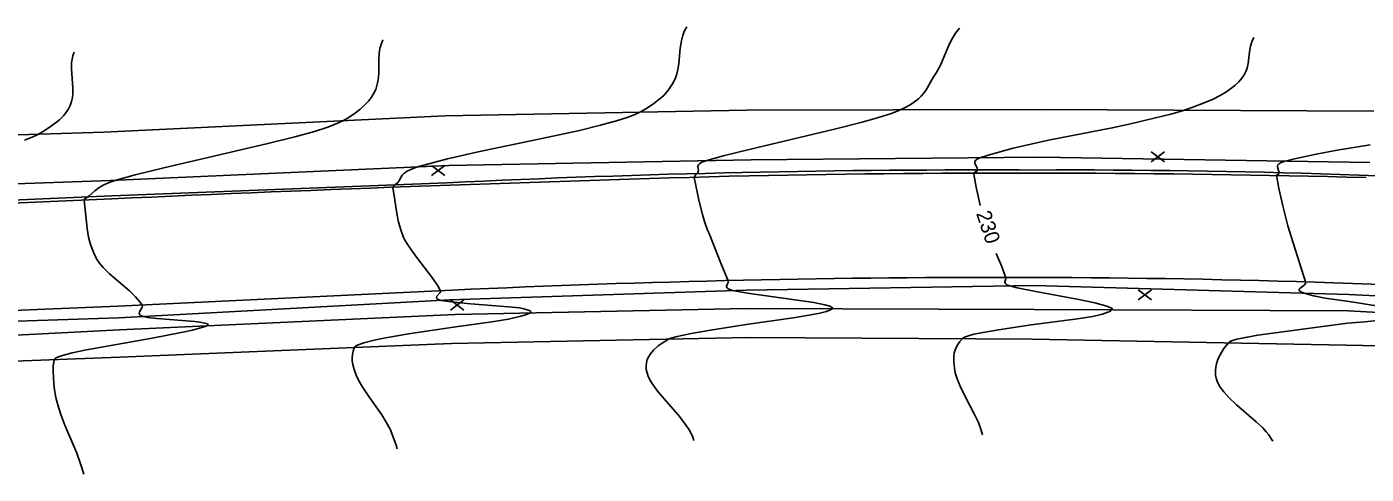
# Model space of a CAD drawing. Extents: x -593772 to -592667, y -1183541 to -1183371.
# Drawn here: x -593539.2 to -593464.5, y -1183400.6 to -1183375.6 of the extents above; entities that cross this region are included whole.
import ezdxf

# ---------------------------------------------------------------- set-up
doc = ezdxf.new("R2010")
doc.units = 0
for name, color, linetype in [('bez obruby', 7, 'Continuous'), ('hlavni vrstevnice', 7, 'Continuous'), ('svisle dopravni znaceni', 7, 'Continuous'), ('terenni hrany', 7, 'Continuous'), ('vodorovne dopravni znaceni', 7, 'Continuous'), ('vrstevnice', 7, 'Continuous')]:
    doc.layers.add(name, color=color, linetype=linetype)

msp = doc.modelspace()

# ---------------------------------------------------------------- linework, layer by layer
at = {"layer": 'bez obruby'}
for p, q in [((-593515.74, -1183384.35), (-593534.44, -1183385.09)), ((-593534.44, -1183385.09), (-593551.89, -1183385.85)), ((-593515.44, -1183390.35), (-593534.11, -1183391.25)), ((-593534.11, -1183391.25), (-593551.68, -1183391.97))]:
    msp.add_line(p, q, dxfattribs=at)
for centre, radius, start, end in [((-593485.761, -1184010.691), 627.058, 89.728524, 92.74029), ((-593480.94, -1183831.828), 448.192, 85.92367, 90.23652), ((-593484.766, -1184050.264), 660.627, 89.84248, 92.661277), ((-593484.14, -1183918.086), 528.447, 86.25017, 89.87092)]:
    msp.add_arc(centre, radius, start, end, dxfattribs=at)
at = {"layer": 'hlavni vrstevnice'}
for points in [[(-593470.724, -1183376.237), (-593470.837, -1183376.474), (-593470.915, -1183376.726), (-593470.97, -1183377.046), (-593471.042, -1183377.693), (-593471.096, -1183377.947), (-593471.16, -1183378.136), (-593471.251, -1183378.318), (-593471.384, -1183378.507), (-593471.56, -1183378.708), (-593471.78, -1183378.916), (-593472.018, -1183379.109), (-593472.29, -1183379.296), (-593472.598, -1183379.477), (-593472.984, -1183379.675), (-593473.486, -1183379.896), (-593474.116, -1183380.134), (-593474.703, -1183380.328), (-593475.359, -1183380.514), (-593477.674, -1183381.076), (-593478.623, -1183381.285), (-593482.177, -1183381.978), (-593482.752, -1183382.1), (-593484.149, -1183382.429), (-593484.946, -1183382.637), (-593485.599, -1183382.827), (-593486.005, -1183382.96), (-593486.162, -1183383.03), (-593486.254, -1183383.101), (-593486.294, -1183383.173), (-593486.295, -1183383.233), (-593486.251, -1183383.342), (-593486.158, -1183383.524), (-593486.136, -1183383.629), (-593486.146, -1183383.669), (-593486.328, -1183383.803), (-593486.333, -1183383.863), (-593486.21, -1183384.601), (-593486.028, -1183385.441), (-593485.983, -1183385.619)], [(-593485.088, -1183388.297), (-593484.791, -1183388.994), (-593484.552, -1183389.657), (-593484.554, -1183389.724), (-593484.613, -1183389.885), (-593484.613, -1183389.923), (-593484.584, -1183389.985), (-593484.504, -1183390.046), (-593484.342, -1183390.116), (-593483.924, -1183390.227), (-593482.888, -1183390.429), (-593480.485, -1183390.874), (-593479.594, -1183391.066), (-593478.92, -1183391.251), (-593478.697, -1183391.336), (-593478.627, -1183391.38), (-593478.608, -1183391.41), (-593478.615, -1183391.44), (-593478.715, -1183391.519), (-593478.864, -1183391.59), (-593479.166, -1183391.689), (-593479.718, -1183391.815), (-593480.565, -1183391.954), (-593483.142, -1183392.293), (-593484.967, -1183392.561), (-593485.828, -1183392.71), (-593486.336, -1183392.818), (-593486.702, -1183392.92), (-593486.856, -1183392.98), (-593486.961, -1183393.041), (-593487.116, -1183393.211), (-593487.279, -1183393.452), (-593487.37, -1183393.646), (-593487.43, -1183393.848), (-593487.461, -1183394.045), (-593487.466, -1183394.332), (-593487.427, -1183394.705), (-593487.375, -1183394.961), (-593487.27, -1183395.298), (-593487.102, -1183395.707), (-593486.817, -1183396.285), (-593486.315, -1183397.253), (-593486.088, -1183397.747), (-593485.946, -1183398.122), (-593485.857, -1183398.427)]]:
    msp.add_lwpolyline(points, dxfattribs=at)
at = {"layer": 'svisle dopravni znaceni'}
for p, q in [((-593476.455, -1183383.181), (-593475.705, -1183382.619)), ((-593476.455, -1183382.619), (-593475.705, -1183383.181)), ((-593516.605, -1183383.951), (-593515.855, -1183383.389)), ((-593516.605, -1183383.389), (-593515.855, -1183383.951)), ((-593515.545, -1183391.461), (-593514.795, -1183390.899)), ((-593515.545, -1183390.899), (-593514.795, -1183391.461)), ((-593477.175, -1183390.891), (-593476.425, -1183390.329)), ((-593477.175, -1183390.329), (-593476.425, -1183390.891))]:
    msp.add_line(p, q, dxfattribs=at)
at = {"layer": 'terenni hrany'}
for p, q in [((-593499.03, -1183380.29), (-593515.83, -1183380.62)), ((-593482.62, -1183380.26), (-593499.03, -1183380.29)), ((-593464.02, -1183380.35), (-593482.62, -1183380.26)), ((-593515.83, -1183380.62), (-593534.88, -1183381.52)), ((-593534.88, -1183381.52), (-593551.71, -1183382.08)), ((-593515.64, -1183383.39), (-593534.51, -1183384.22)), ((-593498.76, -1183383.07), (-593515.64, -1183383.39)), ((-593482.66, -1183382.92), (-593498.76, -1183383.07)), ((-593464.25, -1183383.22), (-593482.66, -1183382.92)), ((-593534.51, -1183384.22), (-593551.8, -1183384.86)), ((-593482.98, -1183390.1), (-593499.02, -1183390.35)), ((-593465.42, -1183390.59), (-593482.98, -1183390.1)), ((-593515.6, -1183390.89), (-593534.05, -1183391.89)), ((-593499.02, -1183390.35), (-593515.6, -1183390.89)), ((-593449.51, -1183391.42), (-593465.42, -1183390.59)), ((-593499.03, -1183391.37), (-593515.28, -1183391.71)), ((-593482.97, -1183391.43), (-593499.03, -1183391.37)), ((-593465.44, -1183391.5), (-593482.97, -1183391.43)), ((-593449.59, -1183392.38), (-593465.44, -1183391.5)), ((-593534.05, -1183391.89), (-593551.71, -1183392.47)), ((-593515.28, -1183391.71), (-593534.01, -1183392.56)), ((-593534.01, -1183392.56), (-593551.8, -1183393.5)), ((-593498.92, -1183393), (-593515.48, -1183393.33)), ((-593483.08, -1183393.08), (-593498.92, -1183393)), ((-593465.57, -1183393.42), (-593483.08, -1183393.08)), ((-593515.48, -1183393.33), (-593533.98, -1183394.1)), ((-593449.56, -1183393.79), (-593465.57, -1183393.42)), ((-593533.98, -1183394.1), (-593551.65, -1183394.76))]:
    msp.add_line(p, q, dxfattribs=at)
at = {"layer": 'vodorovne dopravni znaceni'}
msp.add_line((-593534.44, -1183385.25), (-593551.87, -1183386.03), dxfattribs=at)
for centre, radius, start, end in [((-593445.258, -1185352.875), 1969.645, 91.560035, 92.595148), ((-593483.843, -1184133.894), 750.085, 88.518486, 91.14869)]:
    msp.add_arc(centre, radius, start, end, dxfattribs=at)
at = {"layer": 'vrstevnice'}
for points in [[(-593502.354, -1183375.638), (-593502.478, -1183375.873), (-593502.574, -1183376.111), (-593502.66, -1183376.427), (-593502.722, -1183376.827), (-593502.802, -1183377.712), (-593502.854, -1183378.032), (-593502.938, -1183378.349), (-593503.026, -1183378.581), (-593503.146, -1183378.818), (-593503.373, -1183379.158), (-593503.647, -1183379.469), (-593503.932, -1183379.728), (-593504.193, -1183379.93), (-593504.548, -1183380.165), (-593504.91, -1183380.375), (-593505.059, -1183380.452), (-593505.288, -1183380.556), (-593505.692, -1183380.71), (-593506.273, -1183380.896), (-593507.173, -1183381.142), (-593508.349, -1183381.425), (-593510.349, -1183381.86), (-593513.994, -1183382.621), (-593515.711, -1183383.014), (-593516.756, -1183383.289), (-593517.38, -1183383.47), (-593517.716, -1183383.588), (-593517.962, -1183383.705), (-593518.127, -1183383.819), (-593518.233, -1183383.933), (-593518.423, -1183384.272), (-593518.475, -1183384.337), (-593518.633, -1183384.466), (-593518.745, -1183384.571), (-593518.754, -1183384.619), (-593518.663, -1183385.199), (-593518.543, -1183386.069), (-593518.445, -1183386.554), (-593518.301, -1183387.04), (-593518.154, -1183387.407), (-593518.099, -1183387.52), (-593517.875, -1183387.877), (-593517.493, -1183388.427), (-593516.531, -1183389.695), (-593516.255, -1183390.106), (-593516.092, -1183390.39), (-593516.088, -1183390.434), (-593516.128, -1183390.507), (-593516.3, -1183390.691), (-593516.326, -1183390.763), (-593516.304, -1183390.816), (-593516.23, -1183390.867), (-593516.061, -1183390.923), (-593515.494, -1183391.01), (-593514.426, -1183391.107), (-593512.305, -1183391.274), (-593511.683, -1183391.348), (-593511.454, -1183391.391), (-593511.204, -1183391.462), (-593511.099, -1183391.509), (-593511.047, -1183391.557), (-593511.051, -1183391.591), (-593511.116, -1183391.64), (-593511.302, -1183391.72), (-593511.618, -1183391.813), (-593512.303, -1183391.963), (-593513.24, -1183392.117), (-593515.372, -1183392.411), (-593517.883, -1183392.799), (-593519.264, -1183393.041), (-593519.802, -1183393.151), (-593520.375, -1183393.295), (-593520.695, -1183393.406), (-593520.844, -1183393.485), (-593520.897, -1183393.536), (-593520.919, -1183393.573), (-593520.977, -1183393.755), (-593521.014, -1183393.939), (-593521.028, -1183394.126), (-593521.022, -1183394.314), (-593520.996, -1183394.506), (-593520.923, -1183394.792), (-593520.811, -1183395.093), (-593520.671, -1183395.385), (-593520.435, -1183395.791), (-593520.099, -1183396.294), (-593519.378, -1183397.312), (-593519.122, -1183397.717), (-593518.913, -1183398.124), (-593518.703, -1183398.647), (-593518.58, -1183399.016), (-593518.525, -1183399.217)], [(-593487.14, -1183375.724), (-593487.356, -1183376.002), (-593487.533, -1183376.28), (-593487.718, -1183376.631), (-593488.211, -1183377.776), (-593488.429, -1183378.2), (-593488.603, -1183378.481), (-593488.996, -1183379.156), (-593489.155, -1183379.371), (-593489.283, -1183379.516), (-593489.432, -1183379.659), (-593489.651, -1183379.832), (-593489.896, -1183379.994), (-593490.216, -1183380.169), (-593490.48, -1183380.296), (-593490.933, -1183380.475), (-593491.669, -1183380.715), (-593492.58, -1183380.974), (-593494.116, -1183381.366), (-593498.882, -1183382.501), (-593500.33, -1183382.855), (-593501.293, -1183383.123), (-593501.51, -1183383.206), (-593501.646, -1183383.287), (-593501.709, -1183383.357), (-593501.735, -1183383.438), (-593501.707, -1183383.695), (-593501.744, -1183383.787), (-593501.849, -1183383.9), (-593501.934, -1183384.017), (-593501.939, -1183384.055), (-593501.667, -1183385.4), (-593501.484, -1183386.132), (-593501.365, -1183386.525), (-593501.217, -1183386.949), (-593501.076, -1183387.281), (-593500.461, -1183388.838), (-593500.053, -1183389.827), (-593500.043, -1183389.883), (-593500.075, -1183389.974), (-593500.142, -1183390.108), (-593500.145, -1183390.174), (-593500.113, -1183390.229), (-593500.04, -1183390.283), (-593499.853, -1183390.354), (-593499.605, -1183390.411), (-593498.974, -1183390.513), (-593496.58, -1183390.848), (-593495.266, -1183391.045), (-593494.651, -1183391.166), (-593494.375, -1183391.246), (-593494.24, -1183391.319), (-593494.224, -1183391.354), (-593494.244, -1183391.39), (-593494.336, -1183391.449), (-593494.569, -1183391.54), (-593494.929, -1183391.635), (-593495.428, -1183391.738), (-593496.43, -1183391.905), (-593499.047, -1183392.27), (-593501.042, -1183392.581), (-593502.109, -1183392.772), (-593502.893, -1183392.935), (-593503.25, -1183393.036), (-593503.37, -1183393.087), (-593503.731, -1183393.306), (-593503.957, -1183393.469), (-593504.219, -1183393.705), (-593504.387, -1183393.905), (-593504.481, -1183394.049), (-593504.561, -1183394.226), (-593504.61, -1183394.407), (-593504.628, -1183394.592), (-593504.616, -1183394.781), (-593504.574, -1183394.975), (-593504.504, -1183395.174), (-593504.365, -1183395.45), (-593504.22, -1183395.681), (-593503.969, -1183396.02), (-593503.509, -1183396.559), (-593502.842, -1183397.321), (-593502.434, -1183397.85), (-593502.23, -1183398.156), (-593502.081, -1183398.43), (-593502.018, -1183398.569), (-593501.957, -1183398.748)], [(-593519.31, -1183376.368), (-593519.415, -1183376.63), (-593519.475, -1183376.847), (-593519.522, -1183377.141), (-593519.543, -1183377.511), (-593519.547, -1183378.255), (-593519.58, -1183378.624), (-593519.642, -1183378.917), (-593519.715, -1183379.136), (-593519.813, -1183379.349), (-593519.946, -1183379.567), (-593520.12, -1183379.795), (-593520.372, -1183380.063), (-593520.603, -1183380.269), (-593520.909, -1183380.501), (-593521.296, -1183380.751), (-593521.542, -1183380.891), (-593521.924, -1183381.068), (-593522.447, -1183381.264), (-593523.133, -1183381.484), (-593524.228, -1183381.79), (-593525.802, -1183382.185), (-593531.531, -1183383.514), (-593533.127, -1183383.914), (-593534.197, -1183384.214), (-593534.531, -1183384.325), (-593534.878, -1183384.471), (-593535.142, -1183384.619), (-593535.376, -1183384.797), (-593535.708, -1183385.076), (-593535.834, -1183385.167), (-593535.959, -1183385.269), (-593535.978, -1183385.318), (-593535.808, -1183386.913), (-593535.729, -1183387.386), (-593535.621, -1183387.809), (-593535.465, -1183388.235), (-593535.284, -1183388.603), (-593535.139, -1183388.824), (-593534.918, -1183389.087), (-593534.567, -1183389.431), (-593533.459, -1183390.392), (-593533.107, -1183390.733), (-593532.876, -1183390.998), (-593532.737, -1183391.186), (-593532.724, -1183391.231), (-593532.741, -1183391.307), (-593532.895, -1183391.558), (-593532.912, -1183391.634), (-593532.893, -1183391.698), (-593532.827, -1183391.76), (-593532.686, -1183391.824), (-593532.453, -1183391.875), (-593531.922, -1183391.937), (-593529.804, -1183392.099), (-593529.418, -1183392.151), (-593529.186, -1183392.205), (-593529.102, -1183392.241), (-593529.07, -1183392.281), (-593529.087, -1183392.31), (-593529.181, -1183392.359), (-593529.423, -1183392.444), (-593529.942, -1183392.58), (-593530.558, -1183392.716), (-593532.194, -1183393.036), (-593535.858, -1183393.692), (-593536.653, -1183393.858), (-593537.191, -1183393.997), (-593537.468, -1183394.097), (-593537.583, -1183394.159), (-593537.624, -1183394.19), (-593537.66, -1183394.264), (-593537.702, -1183394.574), (-593537.71, -1183394.882), (-593537.671, -1183395.59), (-593537.639, -1183395.916), (-593537.564, -1183396.343), (-593537.457, -1183396.765), (-593537.287, -1183397.291), (-593537.052, -1183397.901), (-593536.394, -1183399.463), (-593536.175, -1183400.057), (-593536.007, -1183400.634)], [(-593536.545, -1183377.065), (-593536.609, -1183377.263), (-593536.653, -1183377.454), (-593536.682, -1183377.681), (-593536.687, -1183377.986), (-593536.604, -1183379.065), (-593536.609, -1183379.37), (-593536.636, -1183379.597), (-593536.687, -1183379.821), (-593536.767, -1183380.045), (-593536.875, -1183380.262), (-593537.018, -1183380.472), (-593537.135, -1183380.614), (-593537.354, -1183380.833), (-593537.52, -1183380.973), (-593537.854, -1183381.219), (-593538.26, -1183381.483), (-593538.599, -1183381.679), (-593538.881, -1183381.81), (-593539.299, -1183381.969)], [(-593464.222, -1183382.24), (-593466.072, -1183382.54), (-593467.241, -1183382.764), (-593468.46, -1183383.019), (-593468.978, -1183383.146), (-593469.201, -1183383.224), (-593469.317, -1183383.292), (-593469.373, -1183383.35), (-593469.4, -1183383.422), (-593469.4, -1183383.458), (-593469.338, -1183383.667), (-593469.311, -1183383.788), (-593469.331, -1183383.86), (-593469.453, -1183383.936), (-593469.32, -1183384.674), (-593469.095, -1183385.648), (-593468.822, -1183386.761), (-593468.533, -1183387.716), (-593467.824, -1183389.934), (-593467.836, -1183389.985), (-593467.91, -1183390.065), (-593468.141, -1183390.243), (-593468.183, -1183390.303), (-593468.187, -1183390.355), (-593468.152, -1183390.407), (-593468.093, -1183390.449), (-593467.912, -1183390.526), (-593467.397, -1183390.675), (-593466.733, -1183390.8), (-593465.406, -1183390.981), (-593463.876, -1183391.218)], [(-593463.501, -1183392.007), (-593464.526, -1183392.113), (-593465.494, -1183392.202), (-593468.421, -1183392.582), (-593470.49, -1183392.874), (-593471.19, -1183392.988), (-593471.676, -1183393.093), (-593471.972, -1183393.186), (-593472.073, -1183393.235), (-593472.138, -1183393.286), (-593472.386, -1183393.611), (-593472.528, -1183393.828), (-593472.665, -1183394.089), (-593472.745, -1183394.279), (-593472.804, -1183394.466), (-593472.843, -1183394.65), (-593472.863, -1183394.831), (-593472.854, -1183395.096), (-593472.822, -1183395.268), (-593472.769, -1183395.438), (-593472.731, -1183395.529), (-593472.59, -1183395.778), (-593472.403, -1183396.027), (-593472.106, -1183396.352), (-593471.681, -1183396.749), (-593470.585, -1183397.702), (-593470.242, -1183398.032), (-593470.024, -1183398.27), (-593469.889, -1183398.438), (-593469.764, -1183398.619), (-593469.666, -1183398.793)]]:
    msp.add_lwpolyline(points, dxfattribs=at)

# ---------------------------------------------------------------- texts
at = {"layer": 'hlavni vrstevnice'}
msp.add_text('230', height=0.8351, rotation=288.44773, dxfattribs=at).set_placement((-593486.223, -1183386.069))

doc.saveas('drawing.dxf')
